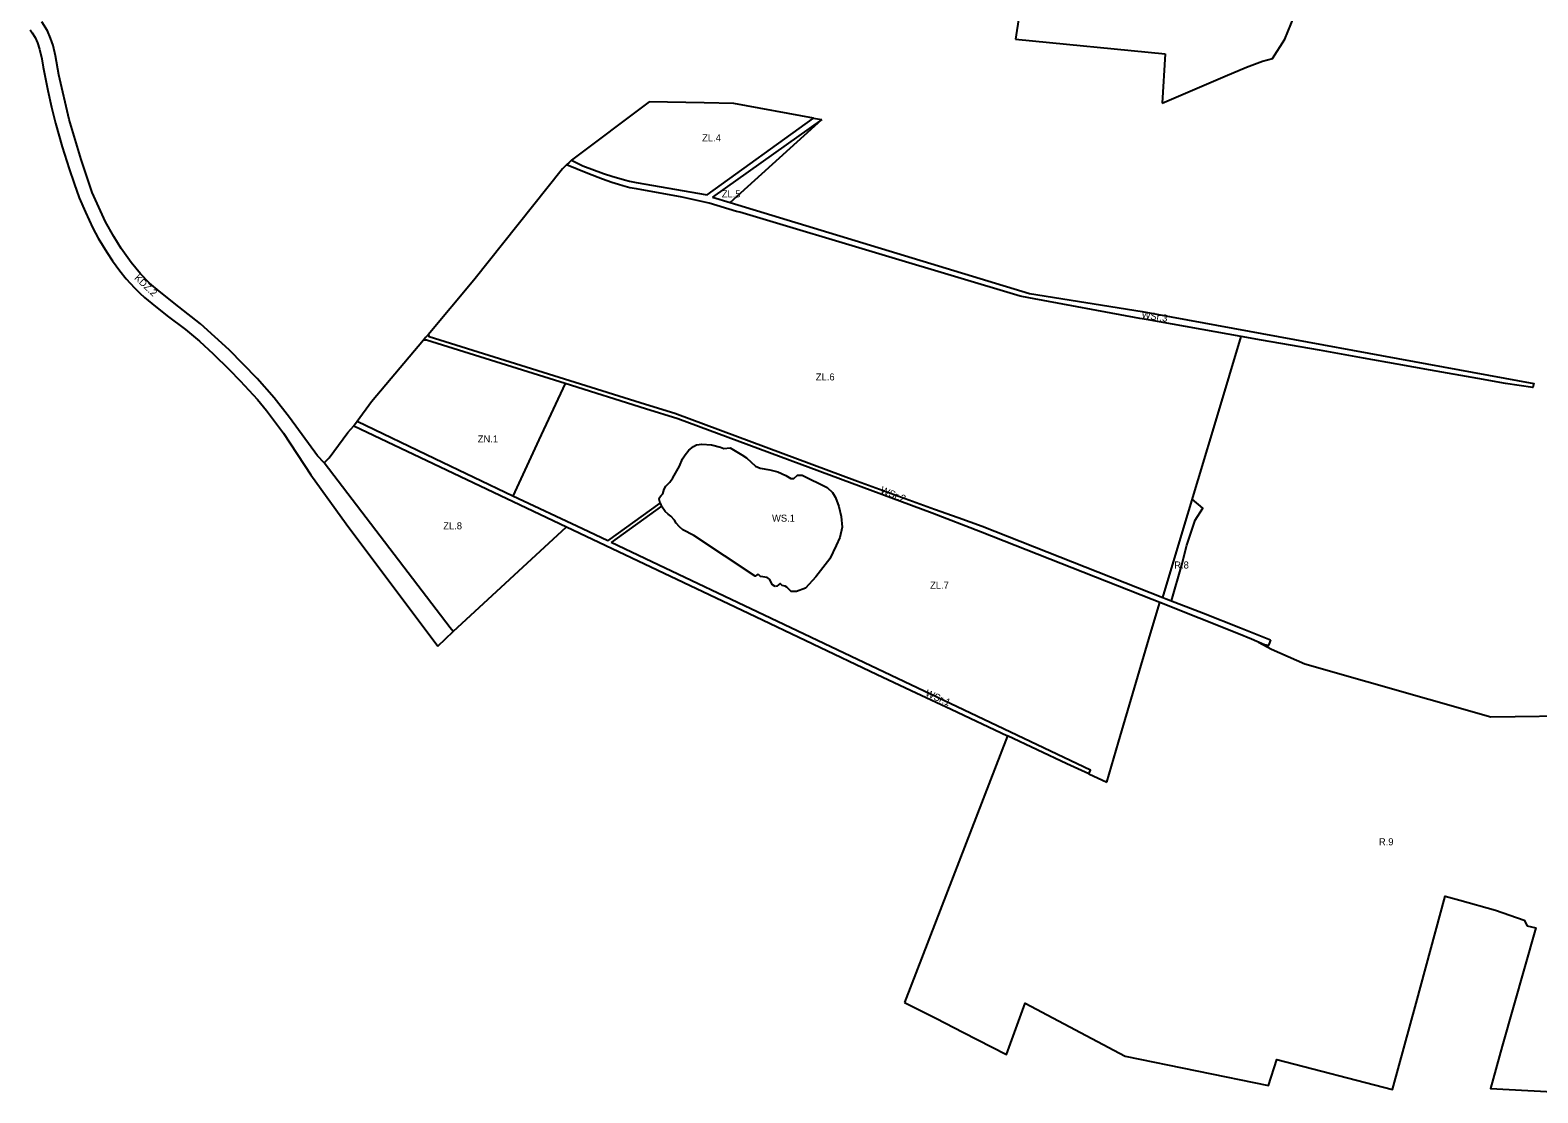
# Model space of a CAD drawing. Extents: x 7418237 to 7420198, y 5543414 to 5545133.
# Drawn here: x 7418338 to 7419412, y 5543417 to 5544174 of the extents above; entities that cross this region are included whole.
import ezdxf

# ---------------------------------------------------------------- set-up
doc = ezdxf.new("R2010")
doc.units = 0
doc.layers.add('linie rozgraniczające', color=7, linetype='Continuous')
doc.layers.add('przeznaczenia terenów', color=7, linetype='Continuous')

msp = doc.modelspace()

# ---------------------------------------------------------------- linework, layer by layer
at = {"layer": 'linie rozgraniczające'}
for p, q in [((7419047.5, 5544218.9), (7419039.6, 5544167.5)), ((7419039.6, 5544167.5), (7419146.2, 5544157)), ((7419146.2, 5544157), (7419144.1, 5544122)), ((7419204.3, 5544147.6), (7419215.7, 5544151.9)), ((7418778.7, 5544123), (7418723.4, 5544081.3)), ((7418817.8, 5544122.1), (7418778.7, 5544123)), ((7418839.1, 5544121.8), (7418817.8, 5544122.1)), ((7418901.7, 5544110.2), (7418823.9, 5544055)), ((7418836.4, 5544051.2), (7418901.7, 5544110.2)), ((7418719.9, 5544077.9), (7418717, 5544075.1)), ((7418734.9, 5544071.8), (7418719.9, 5544077.9)), ((7418723.4, 5544081.3), (7418731.4, 5544077.3)), ((7418731.4, 5544077.3), (7418746.2, 5544071.8)), ((7418745.5, 5544067.7), (7418734.9, 5544071.8)), ((7418760, 5544063.1), (7418756.8, 5544064.1)), ((7418764.9, 5544061.7), (7418760, 5544063.1)), ((7418764.7, 5544066.3), (7418769.5, 5544065.5)), ((7418769.7, 5544060.9), (7418764.9, 5544061.7)), ((7418802.2, 5544055), (7418769.7, 5544060.9)), ((7418823.9, 5544055), (7418836.4, 5544051.2)), ((7418843.2, 5544044.2), (7418841, 5544044.8)), ((7419183.7, 5543900.1), (7419200.5, 5543955.6)), ((7418776, 5543907.6), (7418797, 5543901)), ((7419155.7, 5543807), (7419183.7, 5543900.1)), ((7418547.1, 5543865.7), (7418542.4, 5543870.7)), ((7418802.5, 5543868.5), (7418804.4, 5543871.3)), ((7418804.4, 5543871.3), (7418807, 5543874.8)), ((7418807, 5543874.8), (7418810.2, 5543877.4)), ((7418831.8, 5543875.8), (7418836.3, 5543876.4)), ((7418836.3, 5543876.4), (7418844.8, 5543871.3)), ((7418844.8, 5543871.3), (7418848.1, 5543869.3)), ((7418848.1, 5543869.3), (7418854.5, 5543863.3)), ((7418854.5, 5543863.3), (7418857.8, 5543861.8)), ((7418857.8, 5543861.8), (7418864.7, 5543860.7)), ((7418864.7, 5543860.7), (7418870.3, 5543859.3)), ((7418870.3, 5543859.3), (7418876.1, 5543856.7)), ((7418876.1, 5543856.7), (7418879.6, 5543854.5)), ((7418879.6, 5543854.5), (7418881.7, 5543854.6)), ((7418905.5, 5543848), (7418909.3, 5543844.6)), ((7418785.9, 5543839.9), (7418786, 5543840.9)), ((7418786, 5543840.9), (7418787.2, 5543842.4)), ((7418787.6, 5543834.7), (7418751.6, 5543808.9)), ((7418981.9, 5543832.7), (7418998.7, 5543826.8)), ((7418916.2, 5543819.9), (7418914.4, 5543812.4)), ((7418912, 5543806.7), (7418907.3, 5543797.4)), ((7418914.4, 5543812.4), (7418912, 5543806.7)), ((7419144.6, 5543769.7), (7419155.7, 5543807)), ((7418864.4, 5543782.9), (7418862.8, 5543784)), ((7418866.6, 5543778.8), (7418864.4, 5543782.9)), ((7419150.8, 5543767.3), (7419158.1, 5543792.9)), ((7418868.4, 5543777.5), (7418866.6, 5543778.8)), ((7418628.2, 5543735), (7418639, 5543745.5)), ((7419104.7, 5543638.1), (7419113.1, 5543666.6))]:
    msp.add_line(p, q, dxfattribs=at)
for points in [[(7419215.7, 5544151.9), (7419222.8, 5544153.8), (7419231.5, 5544167.6), (7419237.9, 5544183.2)], [(7418337.8, 5544174.1), (7418339.1, 5544172), (7418341.3, 5544168.7), (7418342.9, 5544164.9), (7418344.4, 5544160.4), (7418346, 5544153.6), (7418347.1, 5544147.5), (7418350.4, 5544130.9), (7418352.9, 5544119.1), (7418355.9, 5544107.7), (7418360.6, 5544090.9), (7418365.6, 5544075.2), (7418369.2, 5544064.7), (7418372.7, 5544054.5), (7418377.2, 5544044.3), (7418382.5, 5544032.9), (7418386.3, 5544025.8), (7418392.3, 5544015.7), (7418396.5, 5544009.5), (7418401.6, 5544002.4), (7418406.1, 5543996.9), (7418412, 5543990.4), (7418416, 5543986.5), (7418419.3, 5543983.5), (7418424.4, 5543979.2), (7418435.4, 5543970.5), (7418448.5, 5543960.7), (7418458.4, 5543952.3), (7418468.1, 5543943.3), (7418479.6, 5543932.1), (7418487.3, 5543924.1), (7418499.7, 5543910.9), (7418506, 5543903), (7418513.3, 5543893.5), (7418518.2, 5543886.8), (7418537.7, 5543857.2)], [(7418542.4, 5543870.7), (7418522.4, 5543898), (7418511.6, 5543912.1), (7418499.4, 5543925.8), (7418479.6, 5543946.1), (7418459.2, 5543964.7), (7418443.7, 5543976.8), (7418429.6, 5543987.9), (7418422.8, 5543993.8), (7418416.4, 5544000.4), (7418409.6, 5544008.5), (7418402.5, 5544018.5), (7418397.3, 5544027), (7418391.5, 5544037.4), (7418382, 5544058.2), (7418374, 5544081.9), (7418365.5, 5544110.4), (7418358.3, 5544142.2), (7418355.8, 5544155.6), (7418354.1, 5544163.1), (7418352.3, 5544168.3), (7418350.1, 5544173.4), (7418346, 5544179.8)], [(7419144.1, 5544122), (7419189, 5544141.1), (7419204.3, 5544147.6)], [(7418769.5, 5544065.5), (7418819.9, 5544056.7), (7418895.7, 5544111.3), (7418839.1, 5544121.8)], [(7418895.7, 5544111.3), (7418898.7, 5544110.8), (7418901.7, 5544110.2)], [(7418717, 5544075.1), (7418653.9, 5543995.8), (7418621.3, 5543957)], [(7418723.4, 5544081.3), (7418721.7, 5544079.6), (7418719.9, 5544077.9)], [(7418756.8, 5544064.1), (7418752.2, 5544065.5), (7418745.5, 5544067.7)], [(7418746.2, 5544071.8), (7418752.8, 5544069.6), (7418757.2, 5544068.4), (7418761.1, 5544067.2), (7418764.7, 5544066.3)], [(7418841, 5544044.8), (7418821.5, 5544050.7), (7418802.2, 5544055)], [(7418836.4, 5544051.2), (7419049.7, 5543986.4), (7419129.8, 5543973.4), (7419408.8, 5543922.1), (7419408.2, 5543919.4), (7419388.7, 5543922.2), (7419368.9, 5543925.7), (7419335.2, 5543931.8), (7419311.6, 5543936), (7419287.5, 5543940.2), (7419256.3, 5543945.9), (7419214.9, 5543953.1), (7419200.5, 5543955.6)], [(7418949.5, 5544012.4), (7418843.2, 5544044.2)], [(7419200.5, 5543955.6), (7419133, 5543967.7), (7419128.3, 5543968.5), (7419049.2, 5543983.3), (7419042.9, 5543984.5), (7418949.5, 5544012.4)], [(7418621.3, 5543957), (7418620.4, 5543956), (7418619.4, 5543955), (7418618.7, 5543954.1), (7418618, 5543953.1)], [(7418621.3, 5543957), (7418621.9, 5543955.6), (7418776, 5543907.6)], [(7418618, 5543953.1), (7418581, 5543909.2), (7418570.6, 5543895.1)], [(7418718.8, 5543922.1), (7418620.1, 5543953), (7418618, 5543953.1)], [(7418718.8, 5543922.1), (7418700.2, 5543882.1), (7418681.7, 5543842), (7418626.1, 5543868.6), (7418570.6, 5543895.1)], [(7418980.4, 5543829.8), (7418799, 5543897), (7418776.1, 5543904.2), (7418718.8, 5543922.1)], [(7418797, 5543901), (7418927.2, 5543852.6), (7418981.9, 5543832.7)], [(7418547.1, 5543865.7), (7418550.8, 5543869.3), (7418564, 5543887.3), (7418568.3, 5543892), (7418719.7, 5543820.2)], [(7418570.6, 5543895.1), (7418569.5, 5543893.5), (7418568.3, 5543892)], [(7418810.2, 5543877.4), (7418812.5, 5543878.5), (7418816.3, 5543879), (7418823, 5543878.4), (7418829.4, 5543876.8), (7418831.8, 5543875.8)], [(7418639, 5543745.5), (7418637, 5543748.1), (7418547.1, 5543865.7)], [(7418793.3, 5543851.8), (7418795.5, 5543855), (7418800.2, 5543863.3), (7418802.5, 5543868.5)], [(7418537.7, 5543857.2), (7418562.9, 5543822.3), (7418628.2, 5543735)], [(7418789.4, 5543847), (7418790.6, 5543849), (7418793.3, 5543851.8)], [(7418881.7, 5543854.6), (7418884.4, 5543856.9), (7418887.8, 5543857), (7418905.5, 5543848)], [(7418749.2, 5543810), (7418731.1, 5543818.6), (7418681.7, 5543842)], [(7418749.2, 5543810), (7418786.5, 5543837), (7418785.9, 5543839.9)], [(7418786.5, 5543837), (7418787.1, 5543835.8), (7418787.6, 5543834.7)], [(7418787.2, 5543842.4), (7418788.4, 5543843.6), (7418789.4, 5543847)], [(7418909.3, 5543844.6), (7418911.5, 5543840.9), (7418913.8, 5543834.5)], [(7419158.1, 5543792.9), (7419161.6, 5543807.1), (7419167.6, 5543824.8), (7419173.1, 5543833.3), (7419165.6, 5543839.9)], [(7418794.1, 5543827.7), (7418792.2, 5543829), (7418790.2, 5543830.9), (7418787.6, 5543834.7)], [(7418798, 5543822.6), (7418796.7, 5543824.9), (7418794.1, 5543827.7)], [(7418913.8, 5543834.5), (7418915.5, 5543827.4), (7418916.2, 5543819.9)], [(7419142.4, 5543766.2), (7419136.9, 5543768.4), (7419014.7, 5543816.5), (7418980.4, 5543829.8)], [(7418998.7, 5543826.8), (7419015.8, 5543820.5), (7419144.6, 5543769.7)], [(7418639, 5543745.5), (7418719.7, 5543820.2), (7418849.4, 5543758.6), (7418941.2, 5543715), (7418969, 5543701.8), (7418993.7, 5543690.2), (7419033.9, 5543671.2), (7418960.5, 5543481.2)], [(7418810.5, 5543813.8), (7418802.7, 5543818), (7418800.2, 5543820.1), (7418798, 5543822.6)], [(7419091.9, 5543644), (7419093.1, 5543646.8), (7418860.5, 5543757.2), (7418780.5, 5543795.1), (7418751.6, 5543808.9)], [(7418862.8, 5543784), (7418858.1, 5543784.8), (7418856.9, 5543785.8), (7418855.8, 5543786.1), (7418854.2, 5543785), (7418810.5, 5543813.8)], [(7418907.3, 5543797.4), (7418897.5, 5543784.4), (7418890, 5543776.3)], [(7418876.7, 5543777.1), (7418875.5, 5543777.7), (7418873.5, 5543778.4), (7418872.1, 5543779.8), (7418869.7, 5543777.9), (7418868.4, 5543777.5)], [(7418890, 5543776.3), (7418883.6, 5543774), (7418879.8, 5543774.1), (7418876.7, 5543777.1)], [(7419113.1, 5543666.6), (7419135.9, 5543744.1), (7419142.4, 5543766.2)], [(7419221.3, 5543739.6), (7419220.5, 5543737.4), (7419219.7, 5543735.2), (7419218.3, 5543735.7), (7419216.9, 5543736.1), (7419207.7, 5543740), (7419198.5, 5543743.8), (7419170.5, 5543755), (7419142.4, 5543766.2)], [(7419144.6, 5543769.7), (7419145.8, 5543769.2), (7419147, 5543768.8), (7419173.5, 5543758.5), (7419200, 5543748.2), (7419210.7, 5543743.9), (7419221.3, 5543739.6)], [(7419150.8, 5543767.3), (7419150.8, 5543767.3)], [(7419624, 5543677.2), (7419602.9, 5543677.8), (7419563.9, 5543680.5), (7419511.5, 5543683.4), (7419447.4, 5543685.5), (7419378.2, 5543684.6), (7419245.8, 5543722.2), (7419222.1, 5543732.6), (7419212.8, 5543737.8)], [(7419091.9, 5543644), (7419084, 5543647.6), (7419076.1, 5543651.2), (7419055, 5543661.2), (7419033.9, 5543671.2)], [(7419091.9, 5543644), (7419104.7, 5543638.1)], [(7418960.5, 5543481.2), (7418983.4, 5543469.9), (7419002.2, 5543460.1), (7419033.2, 5543444.2), (7419046.6, 5543480.6), (7419117.7, 5543443), (7419219.8, 5543422), (7419225.8, 5543440.5), (7419308.1, 5543419.2), (7419325, 5543480.7), (7419345.8, 5543556.9), (7419356.2, 5543554), (7419381.5, 5543547), (7419401.9, 5543539.8), (7419404.1, 5543535.8), (7419410.2, 5543534.3), (7419386.4, 5543450), (7419377.9, 5543420), (7419435.8, 5543416.8)]]:
    msp.add_lwpolyline(points, dxfattribs=at)

# ---------------------------------------------------------------- texts
at = {"layer": 'przeznaczenia terenów'}
for s, p in [('ZL.4', (7418816.4, 5544094.7)), ('ZL.5', (7418830.4, 5544054.8)), ('ZL.6', (7418897.4, 5543924.4)), ('ZN.1', (7418656.6, 5543880.2)), ('WS.1', (7418866.2, 5543823.8)), ('ZL.8', (7418632, 5543818.3)), ('R.8', (7419152.7, 5543790.4)), ('ZL.7', (7418978.8, 5543776)), ('R.9', (7419298.5, 5543593.2))]:
    msp.add_text(s, height=5, dxfattribs=at).set_placement(p)
for s, rotation, p in [('KDZ.2', 316.5157, (7418411.6, 5543996.9)), ('WSr.3', 351.4063, (7419129.2, 5543968.9)), ('WSr.2', 338.1351, (7418943, 5543844.4)), ('WSr.1', 335.813, (7418975, 5543699.9))]:
    msp.add_text(s, height=5, rotation=rotation, dxfattribs=at).set_placement(p)

doc.saveas('drawing.dxf')
